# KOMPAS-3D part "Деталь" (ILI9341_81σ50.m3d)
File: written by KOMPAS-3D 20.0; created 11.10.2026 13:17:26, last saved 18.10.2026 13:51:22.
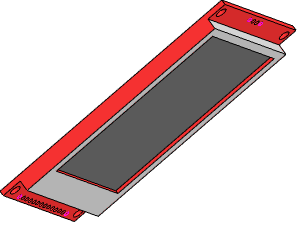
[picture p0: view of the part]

Document properties: Полное имя файла: D:\myProjects\Progect_esp32\box_compas\монитор\ILI9341_81х50.m3d

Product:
- Part/product: Деталь
    Масса: 0.123412

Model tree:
1. Эскиз:1
2. Элемент выдавливания:1
     Расстояние 1 = 1.6
3. Эскиз:2  (with: Элемент выдавливания:1)
4. Элемент выдавливания:2
     Расстояние 2 = 1.6
5. Массив по сетке:1  (with: Элемент выдавливания:2, Эскиз:2)  (4 pattern instances)
     Шаг 1 = 44.2; Угол раствора = -90; Шаг 2 = 75.9
6. Эскиз:3  (with: Элемент выдавливания:1, Элемент выдавливания:2)
7. Элемент выдавливания:3
     Расстояние 1 = 3.4
8. Эскиз:4  (with: Элемент выдавливания:3, Элемент выдавливания:1)
9. Элемент выдавливания:4
     Расстояние 2 = 1
10. Эскиз:5  (with: Элемент выдавливания:1)
11. Элемент выдавливания:5
     Расстояние 2 = 1.6
12. Массив по сетке:2  (with: Элемент выдавливания:5, Эскиз:5)  (14 pattern instances)
     Шаг 1 = 2.54; Угол раствора = 90
13. Эскиз:6  (with: Элемент выдавливания:1)
14. Элемент выдавливания:6
     Расстояние 2 = 1.6
15. Массив по сетке:3  (with: Элемент выдавливания:6, Эскиз:6)  (4 pattern instances)
     Шаг 1 = 2.54; Угол раствора = 90
16. Эскиз:7  (with: Элемент выдавливания:1, Элемент выдавливания:6, Элемент выдавливания:4, Элемент выдавливания:5, Элемент выдавливания:3)

Referenced files in D:\myProjects\Progect_esp32\box_compas\: psb TFT 81_7x50.png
